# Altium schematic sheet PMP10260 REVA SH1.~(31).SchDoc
size 431 x 279 mm; Date: Not shown in title block; ApprovedBy: Not shown in title block; CheckedBy: Not shown in title block; Author: Not shown in title block; CompanyName: Not shown in title block; Engineer: Not shown in title block; Organization: Not shown in title block; Address1: Not shown in title block; Address2: Not shown in title block; Address3: Not shown in title block; Address4: Not shown in title block; DocumentNumber: 1; Revision: Use project parameter SCH_Rev; SheetNumber: 1; SheetTotal: 3; PageSetup: Record=PageOptions|CenterHorizontal=True|CenterVertical=True|PrintScale=1.00|XCorrection=1.00|YCorrection=1.00|PrintKind=0|BorderSize=5000000|LeftOffset=0|BottomOffset=0|Orientation=2|PaperLength=1000|PaperWidth=1000|Scale=100|PaperSource=15|PrintQuality=600|MediaType=1|DitherType=10|PaperKind=Letter|PrintScaleMode=1
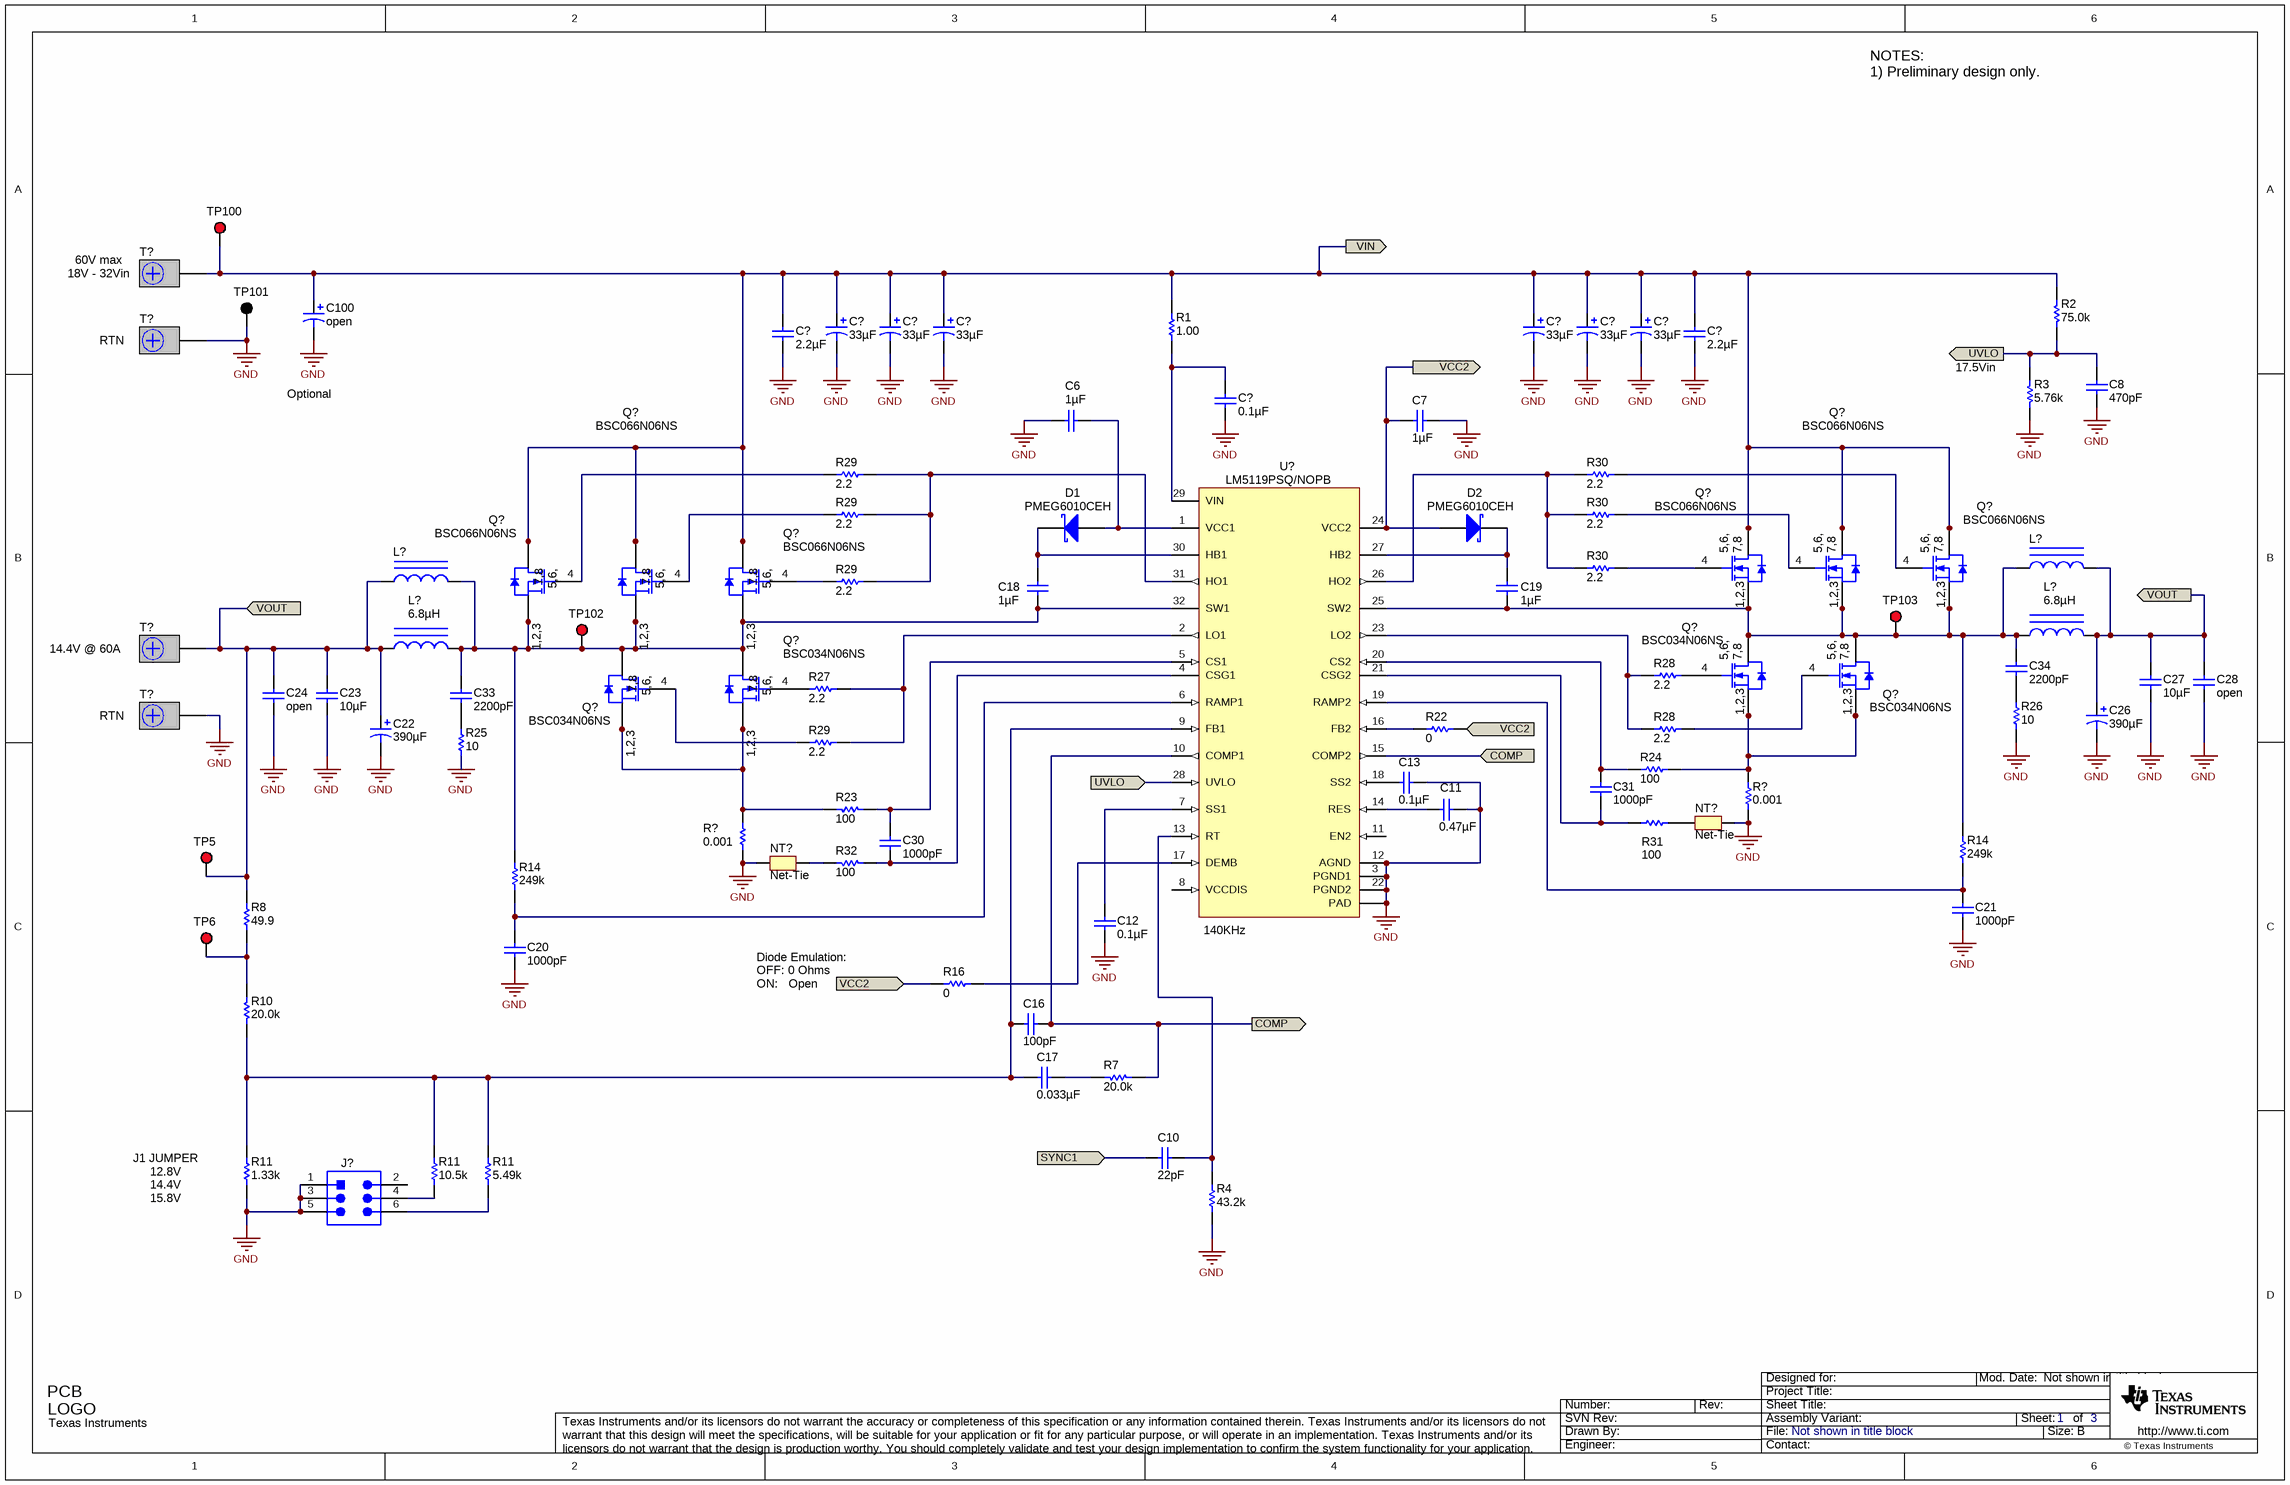
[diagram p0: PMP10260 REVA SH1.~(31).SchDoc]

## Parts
(Parts that share a designator on the sheet are numbered #1, #2 ... from top to bottom, then left to right.)
C6  ValueDisplayed: 1µF  [0603L]  (hidden comment: C1608X7R1E105K080AB)
C7  ValueDisplayed: 1µF  [0603L]  (hidden comment: C1608X7R1E105K080AB)
C8  ValueDisplayed: 470pF  [0603]  (hidden comment: C1608C0G1H471J)
C10  ValueDisplayed: 22pF  [0603]  (hidden comment: C1608C0G1H220J)
C11  ValueDisplayed: 0.47µF  [0603L]  (hidden comment: C0603C474K4RACTU)
C12  ValueDisplayed: 0.1µF  [0603L]  (hidden comment: C1608X7R1H104K)
C13  ValueDisplayed: 0.1µF  [0603L]  (hidden comment: C1608X7R1H104K)
C16  ValueDisplayed: 100pF  [0603]  (hidden comment: C1608C0G1H101J)
C17  ValueDisplayed: 0.033µF  [0603]  (hidden comment: GRM188R71H333KA61D)
C18  ValueDisplayed: 1µF  [0603L]  (hidden comment: C1608X7R1E105K080AB)
C19  ValueDisplayed: 1µF  [0603L]  (hidden comment: C1608X7R1E105K080AB)
C20  ValueDisplayed: 1000pF  [0603]  (hidden comment: C1608C0G1H102J)
C21  ValueDisplayed: 1000pF  [0603]  (hidden comment: C1608C0G1H102J)
C22  ValueDisplayed: 390µF  [SM_RADIAL_8MM]  (hidden comment: 20SVPF390M)
C23  ValueDisplayed: 10µF  [1210L]  (hidden comment: GMK325AB7106MM-T)
C24  ValueDisplayed: open  [1210]
C26  ValueDisplayed: 390µF  [SM_RADIAL_8MM]  (hidden comment: 20SVPF390M)
C27  ValueDisplayed: 10µF  [1210L]  (hidden comment: GMK325AB7106MM-T)
C28  ValueDisplayed: open  [1210]
C30  ValueDisplayed: 1000pF  [0603]  (hidden comment: C1608C0G1H102J)
C31  ValueDisplayed: 1000pF  [0603]  (hidden comment: C1608C0G1H102J)
C33  ValueDisplayed: 2200pF  [0603L]  (hidden comment: C0603C222K5RAC)
C34  ValueDisplayed: 2200pF  [0603L]  (hidden comment: C0603C222K5RAC)
C100  ValueDisplayed: open  [SM_RADIAL_8MM]
C?#1  ValueDisplayed: 2.2µF  [1210]  (hidden comment: GRM32ER72A225KA35L)
C?#2  ValueDisplayed: 33µF  [SXV_E12]  (hidden comment: 63SXV33M)
C?#3  ValueDisplayed: 33µF  [SXV_E12]  (hidden comment: 63SXV33M)
C?#4  ValueDisplayed: 33µF  [SXV_E12]  (hidden comment: 63SXV33M)
C?#5  ValueDisplayed: 33µF  [SXV_E12]  (hidden comment: 63SXV33M)
C?#6  ValueDisplayed: 33µF  [SXV_E12]  (hidden comment: 63SXV33M)
C?#7  ValueDisplayed: 33µF  [SXV_E12]  (hidden comment: 63SXV33M)
C?#8  ValueDisplayed: 2.2µF  [1210]  (hidden comment: GRM32ER72A225KA35L)
C?#9  ValueDisplayed: 0.1µF  [0805_HV]  (hidden comment: C2012X7R2A104K)
D1  PMEG6010CEH  [SOD-123F]
D2  PMEG6010CEH  [SOD-123F]
J?  PEC03DAAN  [SULLINS_PEC03DAAN]  (value not drawn)
L?#1  (no value)  [XAL1510]
L?#2  (no value)  [XAL1510]
L?#3  ValueDisplayed: 6.8µH  [SER2915]  (hidden comment: SER2915H-682KL)
L?#4  ValueDisplayed: 6.8µH  [SER2915]  (hidden comment: SER2915H-682KL)
Logo1  Texas Instruments  [TI_Stacked_Overlay_Small]  (no BOM)
NT?#1  Net-Tie  [Net-Tie_10mil]  (net tie, no BOM)
NT?#2  Net-Tie  [Net-Tie_10mil]  (net tie, no BOM)
Q?#1  BSC066N06NS  [PG-TDSON-8]
Q?#2  BSC066N06NS  [PG-TDSON-8]
Q?#3  BSC066N06NS  [PG-TDSON-8]
Q?#4  BSC066N06NS  [PG-TDSON-8]
Q?#5  BSC066N06NS  [PG-TDSON-8]
Q?#6  BSC066N06NS  [PG-TDSON-8]
Q?#7  BSC034N06NS  [PG-TDSON-8]
Q?#8  BSC034N06NS  [PG-TDSON-8]
Q?#9  BSC034N06NS  [PG-TDSON-8]
Q?#10  BSC034N06NS  [PG-TDSON-8]
R1  value 1.00  [0805_HV]  (hidden comment: CRCW08051R00FKEA)
R2  value 75.0k  [0603]  (hidden comment: CRCW060375K0FKEA)
R3  value 5.76k  [0603]  (hidden comment: CRCW06035K76FKEA)
R4  value 43.2k  [0603]  (hidden comment: CRCW060343K2FKEA)
R7  value 20.0k  [0603]  (hidden comment: CRCW060320K0FKEA)
R8  value 49.9  [0603]  (hidden comment: CRCW060349R9FKEA)
R10  value 20.0k  [0603L]  (hidden comment: CRCW060320K0FKEA)
R11#1  value 1.33k  [0603]  (hidden comment: CRCW06031K33FKEA)
R11#2  value 10.5k  [0603]  (hidden comment: CRCW060310K5FKEA)
R11#3  value 5.49k  [0603]  (hidden comment: CRCW06035K49FKEA)
R14#1  value 249k  [0603]  (hidden comment: CRCW0603249KFKEA)
R14#2  value 249k  [0603]  (hidden comment: CRCW0603249KFKEA)
R16  value 0  [0603L]  (hidden comment: CRCW06030000Z0EA)
R22  value 0  [0603L]  (hidden comment: CRCW06030000Z0EA)
R23  value 100  [0603L]  (hidden comment: RC0603FR-07100RL)
R24  value 100  [0603L]  (hidden comment: RC0603FR-07100RL)
R25  value 10  [2010M]  (hidden comment: CRCW201010R0JNEFHP)
R26  value 10  [2010M]  (hidden comment: CRCW201010R0JNEFHP)
R27  value 2.2  [0603L]  (hidden comment: CRCW06032R20JNEA)
R28#1  value 2.2  [0603L]  (hidden comment: CRCW06032R20JNEA)
R28#2  value 2.2  [0603L]  (hidden comment: CRCW06032R20JNEA)
R29#1  value 2.2  [0603L]  (hidden comment: CRCW06032R20JNEA)
R29#2  value 2.2  [0603L]  (hidden comment: CRCW06032R20JNEA)
R29#3  value 2.2  [0603L]  (hidden comment: CRCW06032R20JNEA)
R29#4  value 2.2  [0603L]  (hidden comment: CRCW06032R20JNEA)
R30#1  value 2.2  [0603L]  (hidden comment: CRCW06032R20JNEA)
R30#2  value 2.2  [0603L]  (hidden comment: CRCW06032R20JNEA)
R30#3  value 2.2  [0603L]  (hidden comment: CRCW06032R20JNEA)
R31  value 100  [0603L]  (hidden comment: RC0603FR-07100RL)
R32  value 100  [0603L]  (hidden comment: RC0603FR-07100RL)
R?#1  value 0.001  [2512M]  (hidden comment: ERJ-M1WTF1M0U)
R?#2  value 0.001  [2512M]  (hidden comment: ERJ-M1WTF1M0U)
T?#1  CB35-36-CY  [CB35-36-CY]  (value not drawn)
T?#2  CB35-36-CY  [CB35-36-CY]  (value not drawn)
T?#3  CB70-14-CY  [CB70-14-CY]  (value not drawn)
T?#4  CB70-14-CY  [CB70-14-CY]  (value not drawn)
TP5  5010  [Keystone5010]  (value not drawn)
TP6  5010  [Keystone5010]  (value not drawn)
TP100  5010  [Keystone5010]  (value not drawn)
TP101  5011  [Keystone5011]  (value not drawn)
TP102  5010  [Keystone5010]  (value not drawn)
TP103  5010  [Keystone5010]  (value not drawn)
U?  LM5119PSQ/NOPB  [RTV0032A]

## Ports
COMP, SYNC1, UVLO, VCC2, VIN, VOUT

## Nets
GND: C6.2 C7.2 C8.2 C11.1 C12.2 C13.1 C20.2 C21.2 C22.2(-) C23.2 C24.2 C26.2(-) C27.2 C28.2 C100.2(-) C?#1.2 C?#2.2(-) C?#3.2(-) C?#4.2(-) C?#5.2(-) C?#6.2(-) C?#7.2(-) C?#8.2 C?#9.2 J?.1 J?.3 J?.5 NT?#1.2 NT?#2.1 R3.1 R4.1 R11#1.1 R25.1 R26.1 R?#1.1 R?#2.1 T?#2.1 T?#4.1 TP101.1 U?.3(PGND1) U?.12(AGND) U?.22(PGND2) U?.33(PAD)
COMP: C16.1 R7.1 U?.10(COMP1) U?.15(COMP2) ; port COMP
SYNC1: C10.2 ; port SYNC1
UVLO: C8.1 R2.1 R3.2 U?.28(UVLO) ; port UVLO
VCC2: C7.1 D2.2(A) R16.1 R22.2 U?.24(VCC2) ; port VCC2
VIN: C100.1(+) C?#1.1 C?#2.1(+) C?#3.1(+) C?#4.1(+) C?#5.1(+) C?#6.1(+) C?#7.1(+) C?#8.1 Q?#1.5(D) Q?#1.6(D) Q?#1.7(D) Q?#1.8(D) Q?#1.9(D) Q?#2.5(D) Q?#2.6(D) Q?#2.7(D) Q?#2.8(D) Q?#2.9(D) Q?#3.5(D) Q?#3.6(D) Q?#3.7(D) Q?#3.8(D) Q?#3.9(D) Q?#4.5(D) Q?#4.6(D) Q?#4.7(D) Q?#4.8(D) Q?#4.9(D) Q?#5.5(D) Q?#5.6(D) Q?#5.7(D) Q?#5.8(D) Q?#5.9(D) Q?#6.5(D) Q?#6.6(D) Q?#6.7(D) Q?#6.8(D) Q?#6.9(D) R1.1 R2.2 T?#1.1 TP100.1 ; port VIN
VOUT: C22.1(+) C23.1 C24.1 C26.1(+) C27.1 C28.1 L?#1.2 L?#2.1 L?#3.2 L?#4.1 R8.2 T?#3.1 TP5.1 ; port VOUT
NetC6_1: C6.1 D1.2(A) U?.1(VCC1)
NetC10_1: C10.1 R4.2 U?.13(RT)
NetC11_2: C11.2 U?.14(RES)
NetC12_1: C12.1 U?.7(SS1)
NetC13_2: C13.2 U?.18(SS2)
NetC16_2: C16.2 C17.2 R10.1 R11#1.2 R11#2.2 R11#3.2 U?.9(FB1)
NetC17_1: C17.1 R7.2
NetC18_1: C18.1 D1.1(K) U?.30(HB1)
NetC18_2: C18.2 C33.1 L?#2.2 L?#4.2 Q?#4.1(S) Q?#4.2(S) Q?#4.3(S) Q?#5.1(S) Q?#5.2(S) Q?#5.3(S) Q?#6.1(S) Q?#6.2(S) Q?#6.3(S) Q?#9.5(D) Q?#9.6(D) Q?#9.7(D) Q?#9.8(D) Q?#9.9(D) Q?#10.5(D) Q?#10.6(D) Q?#10.7(D) Q?#10.8(D) Q?#10.9(D) R14#2.2 TP102.1 U?.32(SW1)
NetC19_1: C19.1 D2.1(K) U?.27(HB2)
NetC19_2: C19.2 C34.1 L?#1.1 L?#3.1 Q?#1.1(S) Q?#1.2(S) Q?#1.3(S) Q?#2.1(S) Q?#2.2(S) Q?#2.3(S) Q?#3.1(S) Q?#3.2(S) Q?#3.3(S) Q?#7.5(D) Q?#7.6(D) Q?#7.7(D) Q?#7.8(D) Q?#7.9(D) Q?#8.5(D) Q?#8.6(D) Q?#8.7(D) Q?#8.8(D) Q?#8.9(D) R14#1.2 TP103.1 U?.25(SW2)
NetC20_1: C20.1 R14#2.1 U?.6(RAMP1)
NetC21_1: C21.1 R14#1.1 U?.19(RAMP2)
NetC30_1: C30.1 R23.1 U?.5(CS1)
NetC30_2: C30.2 R32.1 U?.4(CSG1)
NetC31_1: C31.1 R24.1 U?.20(CS2)
NetC31_2: C31.2 R31.1 U?.21(CSG2)
NetC33_2: C33.2 R25.2
NetC34_2: C34.2 R26.2
NetC?#9_1: C?#9.1 R1.2 U?.29(VIN)
NetJ?_4: J?.4 R11#2.1
NetJ?_6: J?.6 R11#3.1
NetNT?#1_1: NT?#1.1 R31.2
NetNT?#2_2: NT?#2.2 R32.2
NetQ?#1_4: Q?#1.4(G) R30#3.2
NetQ?#2_4: Q?#2.4(G) R30#2.2
NetQ?#3_4: Q?#3.4(G) R30#1.2
NetQ?#4_4: Q?#4.4(G) R29#1.1
NetQ?#5_4: Q?#5.4(G) R29#2.1
NetQ?#6_4: Q?#6.4(G) R29#3.1
NetQ?#7_1: Q?#7.1(S) Q?#7.2(S) Q?#7.3(S) Q?#8.1(S) Q?#8.2(S) Q?#8.3(S) R24.2 R?#1.2
NetQ?#7_4: Q?#7.4(G) R28#1.2
NetQ?#8_4: Q?#8.4(G) R28#2.2
NetQ?#9_1: Q?#9.1(S) Q?#9.2(S) Q?#9.3(S) Q?#10.1(S) Q?#10.2(S) Q?#10.3(S) R23.2 R?#2.2
NetQ?#9_4: Q?#9.4(G) R29#4.1
NetQ?#10_4: Q?#10.4(G) R27.1
NetR8_1: R8.1 R10.2 TP6.1
NetR16_2: R16.2 U?.17(DEMB)
NetR22_1: R22.1 U?.16(FB2)
NetR27_2: R27.2 R29#4.2 U?.2(LO1)
NetR28#1_1: R28#1.1 R28#2.1 U?.23(LO2)
NetR29#1_2: R29#1.2 R29#2.2 R29#3.2 U?.31(HO1)
NetR30#1_1: R30#1.1 R30#2.1 R30#3.1 U?.26(HO2)

Not connected (* = marked no-connect by the designer): J? 2; U? 8(VCCDIS) 11(EN2)

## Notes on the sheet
- NOTES:
  1) Preliminary design only.
- (near T?#1) 18V - 32Vin
- 60V max
- RTN
- (near R3) 17.5Vin
- Optional
- 14.4V @ 60A
- Diode Emulation:
- OFF: 0 Ohms
- (near U?) 140KHz
- ON:   Open
- 12.8V
- (near R11#1) J1 JUMPER
- 14.4V
- 15.8V

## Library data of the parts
C6 C7 C18 C19 = C1608X7R1E105K080AB: CAP, CERM, 1uF, 25V, +/-10%, X7R, 0603; Manufacturer: TDK; Polarized: N; CompType: Capacitor; U/M: EA; Cap_F: 0.000001; Tolerance_%: 10; Value1: Unknown; VDC_V: 25; TaMin_C: -55; TaMax_C: 125; Cap_Case: 0603
C8 = C1608C0G1H471J: CAP, CERM, 470pF, 50V, +/-5%, C0G/NP0, 0603; Manufacturer: TDK; Polarized: N; CompType: Capacitor; U/M: EA; Cap_F: 0.00000000047; Tolerance_%: 5; ESR_Ohm: 0.0922; Value1: 0.0922 ohm; VDC_V: 50; TaMin_C: -55; TaMax_C: 125
C10 = C1608C0G1H220J: CAP, CERM, 22pF, 50V, +/-5%, C0G/NP0, 0603; Manufacturer: TDK; Polarized: N; CompType: Capacitor; U/M: EA; Cap_F: 0.000000000022; Tolerance_%: 5; ESR_Ohm: 0.3882; Value1: 0.3882 ohm; VDC_V: 50; TaMin_C: -55; TaMax_C: 125
C11 = C0603C474K4RACTU: CAP, CERM, 0.47uF, 16V, +/-10%, X7R, 0603; Manufacturer: Kemet; Polarized: N; CompType: Capacitor; U/M: EA; Cap_F: 0.00000047; Tolerance_%: 10; Value1: Unknown; VDC_V: 16; TaMin_C: -55; TaMax_C: 125; Cap_Case: 0603
C12 C13 = C1608X7R1H104K: CAP, CERM, 0.1uF, 50V, +/-10%, X7R, 0603; Manufacturer: TDK; Polarized: N; CompType: Capacitor; U/M: EA; Cap_F: 0.0000001; Tolerance_%: 10; ESR_Ohm: 0.017; Value1: 0.017 ohm; VDC_V: 50; TaMin_C: -55; TaMax_C: 125; Cap_Case: 0603
C16 = C1608C0G1H101J: CAP, CERM, 100pF, 50V, +/-5%, C0G/NP0, 0603; Manufacturer: TDK; Polarized: N; CompType: Capacitor; U/M: EA; Cap_F: 0.0000000001; Tolerance_%: 5; ESR_Ohm: 0.1679; Value1: 0.1679 ohm; VDC_V: 50; TaMin_C: -55; TaMax_C: 125
C17 = GRM188R71H333KA61D: CAP, CERM, 0.033uF, 50V, +/-10%, X7R, 0603; Manufacturer: MuRata; Polarized: N; CompType: Capacitor; U/M: EA; Cap_F: 0.000000033; Tolerance_%: 10; Value1: Unknown; VDC_V: 50; TaMin_C: -55; TaMax_C: 125
C20 C21 C30 C31 = C1608C0G1H102J: CAP, CERM, 1000pF, 50V, +/-5%, C0G/NP0, 0603; Manufacturer: TDK; Polarized: N; CompType: Capacitor; U/M: EA; Cap_F: 0.000000001; Tolerance_%: 5; ESR_Ohm: 0.0563; Value1: 0.0563 ohm; VDC_V: 50; TaMin_C: -55; TaMax_C: 125
C22 C26 = 20SVP100M: CAP, OS-CON, 390uF, 20V, +/-20%, 0.014 ohm, 8x10 SMD; Manufacturer: Sanyo; Polarized: Y; CompType: Capacitor; U/M: EA; Cap_F: 0.0001; Tolerance_%: 20; ESR_Ohm: 0.024; IRMS_A: 3.32; TaMin_C: -55; TaMax_C: 105; Cap_Case: 8.3x8.3x11.9
C23 C27 = GMK325AB7106MM-T: CAP, CERM, 10uF, 35V, +/-20%, X7R, 1206; Manufacturer: Taiyo Yuden; Polarized: N; CompType: Capacitor; U/M: EA; Cap_F: 0.00001; Tolerance_%: 20; Value1: Unknown; VDC_V: 35; TaMin_C: -55; TaMax_C: 125; Cap_Case: 1210
C24 C28 = C3225X7R1H335M: CAP, CERM, open, 1210; Manufacturer: TDK; Polarized: N; CompType: Capacitor; Value: 10uF; U/M: EA; Cap_F: 0.0000033; Tolerance_%: 20; Value1: Unknown; VDC_V: 50; Value2: 50V; TempCo: X5R; TaMin_C: -55; TaMax_C: 125
C33 C34 = C0603C222K5RAC: CAP, CERM, 2200pF, 50V, +/-10%, X7R, 0603; Manufacturer: Kemet; Polarized: N; CompType: Capacitor; U/M: EA; Cap_F: 0.0000000022; Tolerance_%: 10; Value1: Unknown; VDC_V: 50; TaMin_C: -55; TaMax_C: 125; Cap_Case: 0603
C100 = 20SVP100M: CAP, OS-CON, open; Manufacturer: Sanyo; Polarized: Y; CompType: Capacitor; Value: 82uF; U/M: EA; Cap_F: 0.0001; Tolerance_%: 20; Value1: 0.020 ohm; VDC_V: 35; Value2: 35V; ESR_Ohm: 0.024; IRMS_A: 3.32; TaMin_C: -55; TaMax_C: 105; Cap_Case: 8.3x8.3x11.9
C?#1 C?#8 = GRM32ER72A225KA35L: CAP, CERM, 2.2uF, 100V, +/-10%, X7R, 1210; Manufacturer: MuRata; Polarized: N; CompType: Capacitor; U/M: EA; Cap_F: 0.0000022; Tolerance_%: 10; ESR_Ohm: 0.007; Value1: 0.007 ohm; VDC_V: 100; IRMS_A: 4.4; TaMin_C: -55; TaMax_C: 125
C?#2-C?#7 = 63SXV33M: CAP, OS-CON, 33uF, 63V, +/-20%, 0.025 ohm, 8.0x11.9mm SMD; Manufacturer: Panasonic; Polarized: Y; CompType: Capacitor; U/M: EA; Cap_F: 0.000033; Tolerance_%: 20; VDC_V: 63; ESR_Ohm: 0.025; IRMS_A: 2.95; TaMin_C: -55; TaMax_C: 105
C?#9 = C2012X7R2A104K: CAP, CERM, 0.1uF, 100V, +/-10%, X7R, 0805; Manufacturer: TDK; Polarized: N; CompType: Capacitor; U/M: EA; Cap_F: 0.0000001; Tolerance_%: 10; ESR_Ohm: 0.0158; Value1: 0.0158 ohm; VDC_V: 100; TaMin_C: -55; TaMax_C: 125; Cap_Case: 0805
D1 D2 = PMEG6010CEH,115: Diode, Schottky, 60V, 1A, SOD-123F; Manufacturer: NXP Semiconductor; U/M: EA; Vf_V: 0.57; Value2: 0.57V; Io_A: 1; Vr_V: 60; TJmax_C: 150
J? = PEC03DAAN: Header, 100mil, 3x2, Tin, TH; Manufacturer: Sullins Connector Solutions; SymbolCreator: a0412235; U/M: EA
L?#1 L?#2 = XAL1510-682MEB: Inductor, Shielded, Composite, 6.8uH, 26A, 0.00417 ohm, SMD; Ind_H: 6.8E-6; Imax_A: 26; Irms: 26A @ 40C rise; Isat: 36A @ 30% inductance drop; U/M: EA
L?#3 L?#4 = SER2915H-682KL: Inductor, Shielded E Core, Ferrite, 6.8uH, 30A, 0.00186 ohm, SMD; Manufacturer: Coilcraft; Ind_H: 6.8E-6; Imax_A: 30; Irms: 30A @ 40C rise; Isat: 36.2A @ 30% inductance drop; U/M: EA
Logo1 = TI_Logo: Texas Instrument Corporate Signature; SymbolCreator: codlsc
NT?#1 NT?#2 = Net-Tie: Single point connection between nets.; SymbolCreator: codlsc
Q?#1-Q?#6 = BSC067N06LS3 G: MOSFET, N-CH, 60V, 0.0066 ohm, 17nC, PG-TDSON-8; Manufacturer: Infineon Technologies; Alternate Manufacturer: None; U/M: EA; ChType: N; VdsMax_V: 60; Rdson45_Ohm: 0.0121; Value2: 21 nC; QgTyp_nC: 23; Vgs_V: 20; IdsMax_A: 50
Q?#7-Q?#10 = BSC067N06LS3 G: MOSFET, N-CH, 60V, 0.0034 ohm, 33nC, PG-TDSON-8; Manufacturer: Infineon Technologies; Alternate Manufacturer: None; U/M: EA; ChType: N; VdsMax_V: 60; Rdson45_Ohm: 0.0121; QgTyp_nC: 23; Vgs_V: 20; IdsMax_A: 50
R1 = CRCW08051R00FKEA: RES, 1.00 ohm, 1%, 0.125W, 0805; Manufacturer: Vishay-Dale; CompType: Resistor; Res_ohm: 1; Value_Code: 1R00; Power_W: 0.125; VDC_V: 150; TempCo: 100 ppm/C; EIA_Code: E96; U/M: EA
R2 = CRCW060375K0FKEA: RES, 75.0k ohm, 1%, 0.1W, 0603; Manufacturer: Vishay-Dale; CompType: Resistor; Res_ohm: 75000; Value_Code: 75k0; Tolerance_%: 1; Power_W: 0.1; VDC_V: 75; TempCo: 100 ppm/C; EIA_Code: E96; U/M: EA
R3 = CRCW06035K76FKEA: RES, 5.76k ohm, 1%, 0.1W, 0603; Manufacturer: Vishay-Dale; CompType: Resistor; Res_ohm: 5760; Value_Code: 5k76; Tolerance_%: 1; Power_W: 0.1; VDC_V: 75; TempCo: 100 ppm/C; EIA_Code: E96; U/M: EA
R4 = CRCW060343K2FKEA: RES, 43.2k ohm, 1%, 0.1W, 0603; Manufacturer: Vishay-Dale; CompType: Resistor; Res_ohm: 43200; Value_Code: 43k2; Tolerance_%: 1; Power_W: 0.1; VDC_V: 75; TempCo: 100 ppm/C; EIA_Code: E96; U/M: EA
R7 R10 = CRCW060320K0FKEA: RES, 20.0k ohm, 1%, 0.1W, 0603; Manufacturer: Vishay-Dale; CompType: Resistor; Res_ohm: 20000; Value_Code: 20k0; Tolerance_%: 1; Power_W: 0.1; VDC_V: 75; TempCo: 100 ppm/C; EIA_Code: E96; U/M: EA
R8 = CRCW060349R9FKEA: RES, 49.9 ohm, 1%, 0.1W, 0603; Manufacturer: Vishay-Dale; CompType: Resistor; Value_Code: 49R9; Tolerance_%: 1; Power_W: 0.1; VDC_V: 75; TempCo: 100 ppm/C; EIA_Code: E96; U/M: EA
R11#1 = CRCW06031K33FKEA: RES, 1.33k ohm, 1%, 0.1W, 0603; Manufacturer: Vishay-Dale; CompType: Resistor; Res_ohm: 1330; Value_Code: 1k33; Tolerance_%: 1; Power_W: 0.1; VDC_V: 75; TempCo: 100 ppm/C; EIA_Code: E96; U/M: EA
R11#2 = CRCW060310K5FKEA: RES, 10.5k ohm, 1%, 0.1W, 0603; Manufacturer: Vishay-Dale; CompType: Resistor; Res_ohm: 10500; Value_Code: 10k5; Tolerance_%: 1; Power_W: 0.1; VDC_V: 75; TempCo: 100 ppm/C; EIA_Code: E96; U/M: EA
R11#3 = CRCW06035K49FKEA: RES, 5.49k ohm, 1%, 0.1W, 0603; Manufacturer: Vishay-Dale; CompType: Resistor; Res_ohm: 5490; Value_Code: 5k49; Tolerance_%: 1; Power_W: 0.1; VDC_V: 75; TempCo: 100 ppm/C; EIA_Code: E96; U/M: EA
R14#1 R14#2 = CRCW0603249KFKEA: RES, 249k ohm, 1%, 0.1W, 0603; Manufacturer: Vishay-Dale; CompType: Resistor; Res_ohm: 249000; Tolerance_%: 1; Power_W: 0.1; VDC_V: 75; TempCo: 100 ppm/C; EIA_Code: E96; U/M: EA
R16 R22 = CRCW06030000Z0EA: RES, 0 ohm, 5%, 0.1W, 0603; Manufacturer: Vishay-Dale; CompType: Resistor; Value_Code: 0000; Tolerance_%: 5; Power_W: 0.1; VDC_V: 75; TempCo: 200 ppm/C; EIA_Code: E24; U/M: EA
R23 R24 R31 R32 = RC0603FR-07100RL: RES, 100 ohm, 1%, 0.1W, 0603; Manufacturer: Yageo America; CompType: Resistor; Value_Code: 100R; Tolerance_%: 1; Power_W: 0.1; VDC_V: 150; TempCo: 200 ppm/C; EIA_Code: E96; U/M: EA
R25 R26 = CRCW20101R00JNEFHP: RES, 10 ohm, 5%, 1W, 2010; Manufacturer: Vishay-Dale; CompType: Resistor; Res_ohm: 1; Value_Code: 1R00; Tolerance_%: 5; VDC_V: 400; TempCo: 200 ppm/C; EIA_Code: E24; U/M: EA
R27 R28#1 R28#2 R29#1-R29#4 R30#1-R30#3 = CRCW06032R20JNEA: RES, 2.2 ohm, 5%, 0.1W, 0603; Manufacturer: Vishay-Dale; CompType: Resistor; Value_Code: 2R20; Tolerance_%: 5; Power_W: 0.1; VDC_V: 75; TempCo: 200 ppm/C; EIA_Code: E24; U/M: EA
R?#1 R?#2 = ERJ-M1WTF1M0U: RES, 0.001 ohm, 1%, 1W, 2512; Manufacturer: Panasonic; CompType: Resistor; Value_Code: R001; Tolerance_%: 1; TempCo: ppm/C; EIA_Code: E96; U/M: EA
T?#1 T?#2 = CB35-36-CY: Terminal 50A Lug; Manufacturer: Panduit; SymbolCreator: crossc; CompType: Screw Terminal; U/M: EA
T?#3 T?#4 = CB70-14-CY: Terminal 90A Lug; Manufacturer: Panduit; SymbolCreator: crossc; CompType: Screw Terminal; U/M: EA
TP5 TP6 TP100 TP102 TP103 = 5010: Test Point, Multipurpose, Red, TH; Manufacturer: Keystone; CompType: Test Point Loop; U/M: EA
TP101 = 5011: Test Point, Multipurpose, Black, TH; Manufacturer: Keystone; CompType: Test Point Loop; U/M: EA
U? = LM5119PSQ/NOPB: LM5119/LM5119Q Wide Input Range Dual Synchronous Buck Controller, RTV0032A; Alternate Manufacturer: None; Manufacturer: Texas Instruments; SymbolCreator: a0411947; CompType: IC; U/M: EA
